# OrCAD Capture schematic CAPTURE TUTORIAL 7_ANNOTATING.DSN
size A; title: Transceiver; rev: A; company: EMA Design Automation; note: EMA-1; note: 225 Tech Park Drive; note: Rochester, NY 14623
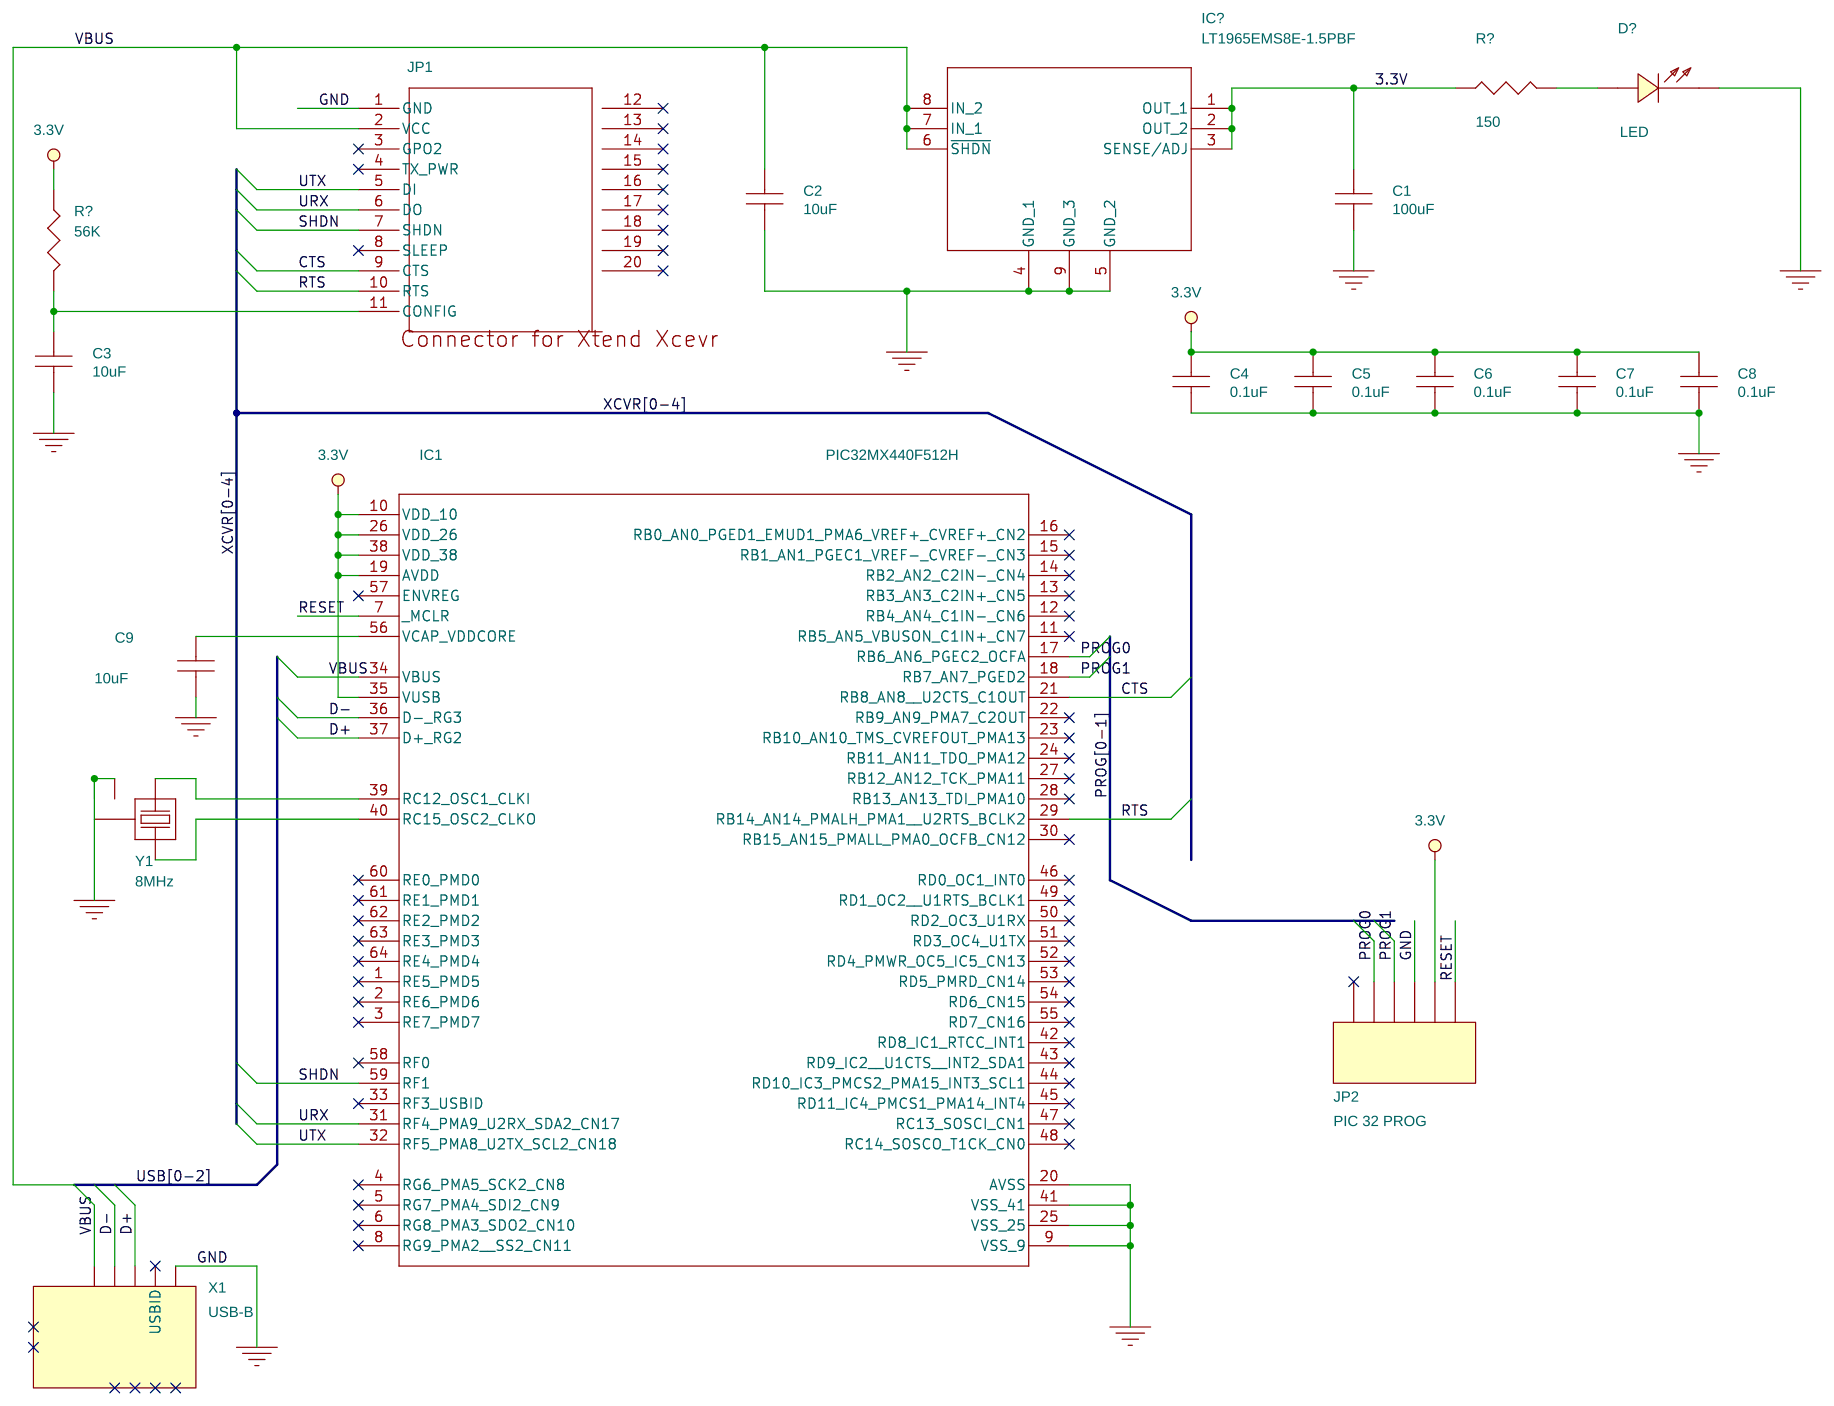
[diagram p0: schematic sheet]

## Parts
C1  100uF  [1210]
C2  10uF  [0402-cap]
C3  10uF  [0402-cap]
C4  0.1uF  [0402-cap]
C5  0.1uF  [0402-cap]
C6  0.1uF  [0402-cap]
C7  0.1uF  [0402-cap]
C8  0.1uF  [0402-cap]
C9  10uF  [0402-cap]
D?#3  LED  [LED_LNJ]
IC1  PIC32MX440F512H  [sqfp-s-10x10-64]
IC?#4  LT1965EMS8E-1.5PBF  [SOP65P490X110-9N]
JP1  XTEND-DIGI-MODEM  [xtend-digi-modem]
JP2  PIC 32 PROG  [1x06_lock]
R?#1  150  [0402-res]
R?#2  56K  [0402-res]
X1  USB-B  [USB-MICROB]
Y1  8MHz  [crystal-smd]

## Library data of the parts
C1-C9 = CAP_NP
D?#3 = LED
IC1 = PIC32MX440F512H
IC?#4 = LT1965EMS8E-1_0.5PBF: 3D_Image_URL: https://componentsearchengine.com/2D/0T/583674.2.1.png; Body_Length: 3.102; Body_Width: 3.102; Category: Integrated Circuit; Confidence: C3 - Community checked; Height: 1.1; Package_Category: Small Outline Packages; Pin_Count: 9; Released_Date: 2017-01-11 17:02:35; Source_Version: 2.1; Status: Released; cdn_id: {"manufacturer":"Linear Technology","manufacturerPartNumber":"LT1965EMS8E-1.5PBF"}
JP1 = XTEND-DIGI-MODEM
JP2 = M06_LOCK
R?#1 R?#2 = RESISTOR
X1 = USB-MICROB
Y1 = CRYSTAL

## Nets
3.3V: C1.1 C4.1 C5.1 C6.1 C7.1 C8.1 IC1.10(VDD) IC1.19(AVDD) IC1.26(VDD) IC1.35(VUSB) IC1.38(VDD) IC?#4.1(OUT) IC?#4.2(OUT) IC?#4.3(SENSE/ADJ) JP2.2 R?#1.1 R?#2.1
GND: C1.2 C2.2 C3.2 C4.2 C5.2 C6.2 C7.2 C8.2 C9.2 D?#3.1(CATHODE) IC1.9(VSS) IC1.20(AVSS) IC1.25(VSS) IC1.41(VSS) IC?#4.4(GND_1) IC?#4.5(GND_2) IC?#4.9(GND_3) JP1.1(GND) JP2.3 X1.GND Y1.2(GND) Y1.4(GND)
VBUS: C2.1 IC1.34(VBUS) IC?#4.6(~{SHDN}) IC?#4.7(IN_1) IC?#4.8(IN_2) JP1.2(VCC) X1.VBUS
CTS: IC1.21(RB8_AN8__U2CTS_C1OUT) JP1.9(CTS)
D+: IC1.37(D+_RG2) X1.D+
D-: IC1.36(D-_RG3) X1.D-
PROG0: IC1.17(RB6_AN6_PGEC2_OCFA) JP2.5
PROG1: IC1.18(RB7_AN7_PGED2) JP2.4
RESET: IC1.7(_MCLR) JP2.1
RTS: IC1.29(RB14_AN14_PMALH_PMA1__U2RTS_BCLK2) JP1.10(RTS)
SHDN: IC1.59(RF1) JP1.7(SHDN)
URX: IC1.31(RF4_PMA9_U2RX_SDA2_CN17) JP1.6(DO)
UTX: IC1.32(RF5_PMA8_U2TX_SCL2_CN18) JP1.5(DI)
N05718: C3.1 JP1.11(CONFIG) R?#2.2
N05832: D?#3.2(ANODE) R?#1.2
N05985: IC1.39(RC12_OSC1_CLKI) Y1.1
N05997: IC1.40(RC15_OSC2_CLKO) Y1.3
N06072: C9.1 IC1.56(VCAP_VDDCORE)

Not connected (* = marked no-connect by the designer): IC1 1(RE5_PMD5)* 2(RE6_PMD6)* 3(RE7_PMD7)* 4(RG6_PMA5_SCK2_CN8)* 5(RG7_PMA4_SDI2_CN9)* 6(RG8_PMA3_SDO2_CN10)* 8(RG9_PMA2__SS2_CN11)* 11(RB5_AN5_VBUSON_C1IN+_CN7)* 12(RB4_AN4_C1IN-_CN6)* 13(RB3_AN3_C2IN+_CN5)* 14(RB2_AN2_C2IN-_CN4)* 15(RB1_AN1_PGEC1_VREF-_CVREF-_CN3)* 16(RB0_AN0_PGED1_EMUD1_PMA6_VREF+_CVREF+_CN2)* 22(RB9_AN9_PMA7_C2OUT)* 23(RB10_AN10_TMS_CVREFOUT_PMA13)* 24(RB11_AN11_TDO_PMA12)* 27(RB12_AN12_TCK_PMA11)* 28(RB13_AN13_TDI_PMA10)* 30(RB15_AN15_PMALL_PMA0_OCFB_CN12)* 33(RF3_USBID)* 42(RD8_IC1_RTCC_INT1)* 43(RD9_IC2__U1CTS__INT2_SDA1)* 44(RD10_IC3_PMCS2_PMA15_INT3_SCL1)* 45(RD11_IC4_PMCS1_PMA14_INT4)* 46(RD0_OC1_INT0)* 47(RC13_SOSCI_CN1)* 48(RC14_SOSCO_T1CK_CN0)* 49(RD1_OC2__U1RTS_BCLK1)* 50(RD2_OC3_U1RX)* 51(RD3_OC4_U1TX)* 52(RD4_PMWR_OC5_IC5_CN13)* 53(RD5_PMRD_CN14)* 54(RD6_CN15)* 55(RD7_CN16)* 57(ENVREG)* 58(RF0)* 60(RE0_PMD0)* 61(RE1_PMD1)* 62(RE2_PMD2)* 63(RE3_PMD3)* 64(RE4_PMD4)*; JP1 3(GPO2)* 4(TX_PWR)* 8(SLEEP)* 12* 13* 14* 15* 16* 17* 18* 19* 20*; JP2 6*; X1 ID(USBID)* MT1* MT2* MT3* MT4* P_1* P_2*
